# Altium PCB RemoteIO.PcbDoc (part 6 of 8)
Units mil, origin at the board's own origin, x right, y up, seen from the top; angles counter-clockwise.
Board outline 7874.02 x 2362.2 mil, 6 copper layers (Top Layer, GND1, Layer 2, PWR, GND2, Bottom Layer), stack 60.956 mil thick; 655 components, 447 nets, 2607 pads, 1444 vias.
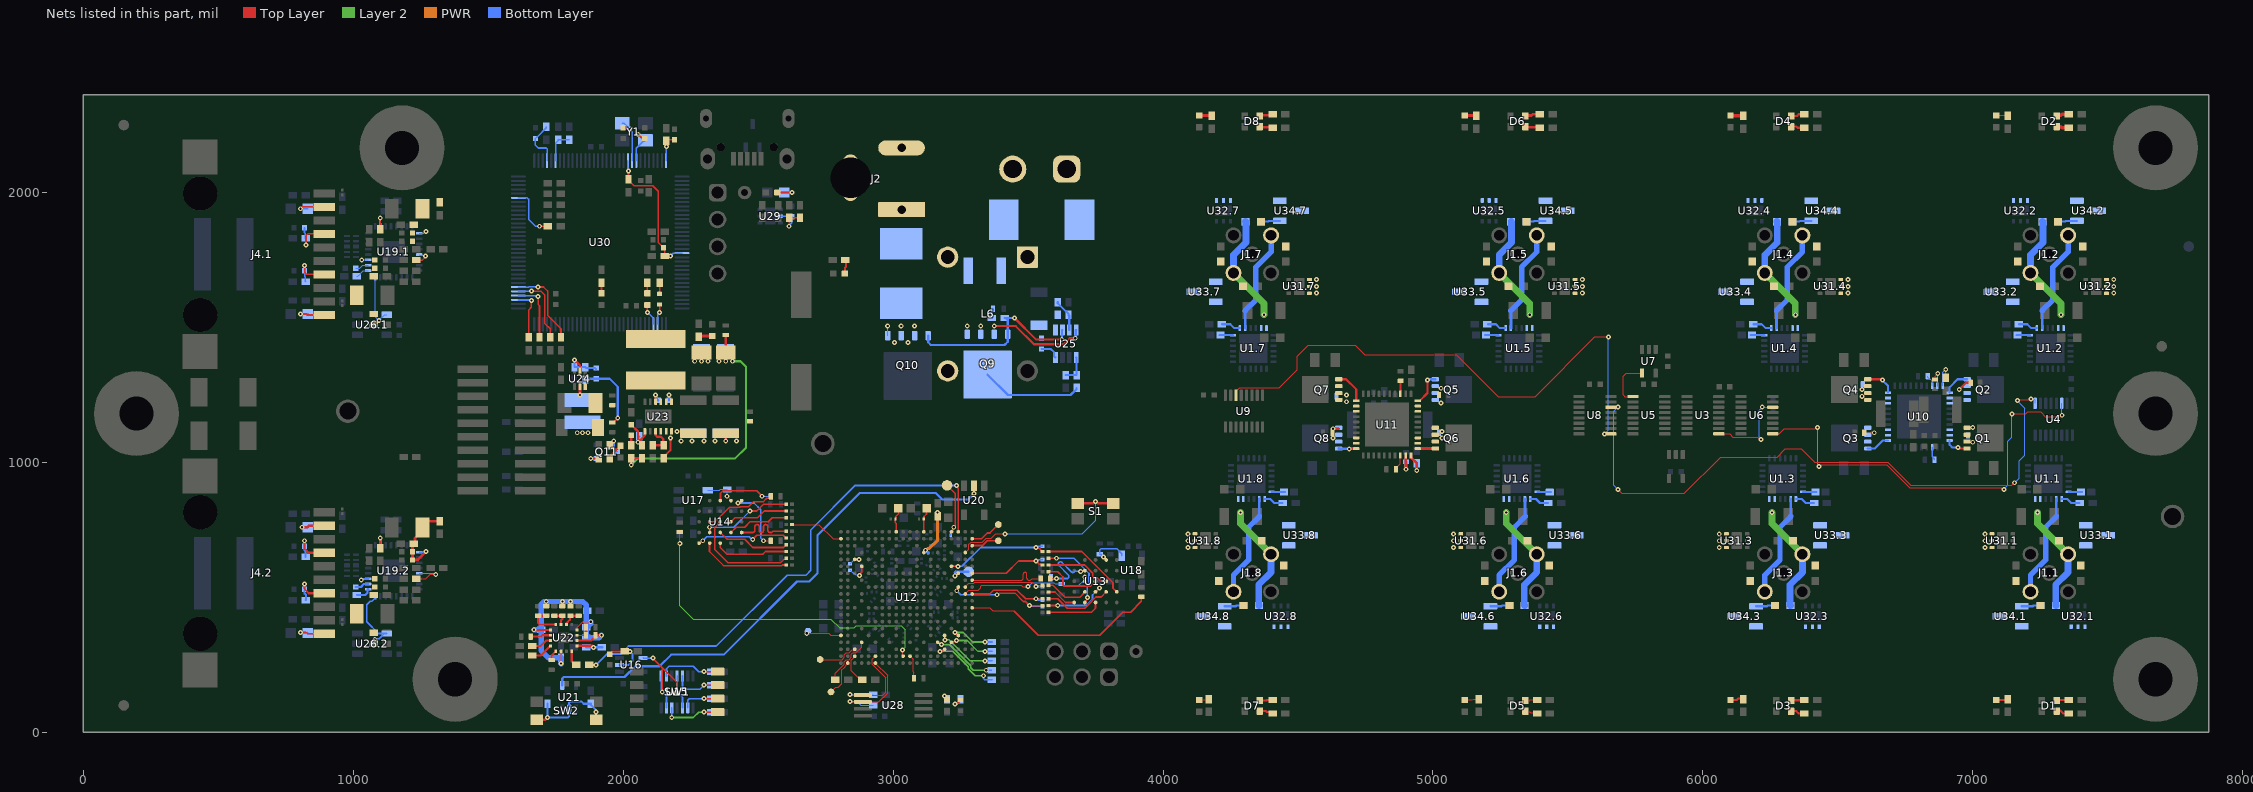
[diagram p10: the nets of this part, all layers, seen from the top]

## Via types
v1: diameter 18, hole 8, Top Layer to Bottom Layer, tented both sides, 1277 vias
v2: diameter 19.68, hole 7.87, Top Layer to Bottom Layer, tented both sides, 133 vias
v3: diameter 19.68, hole 7.87, Top Layer to Bottom Layer, 34 vias

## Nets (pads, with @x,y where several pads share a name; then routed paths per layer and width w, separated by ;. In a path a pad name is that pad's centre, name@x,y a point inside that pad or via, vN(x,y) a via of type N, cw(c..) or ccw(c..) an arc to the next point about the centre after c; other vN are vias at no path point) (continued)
NetC31_2: C31.2 R93.2 U16.2 | length 173.7
  Top Layer w6.45: C31.2@1950,289.69 1960.31,300 R93.2@2006.38,300 v1(2024.87,300)
  Bottom Layer w6.45: U16.2@1985.71,250 2020,250 2034.87,264.87 2034.87,290 v1(2024.87,300)
NetC35_1: C35.1 R100.1 SW2.2 SW2.4 U21.2 | length 381.1
  Top Layer w8: SW2.4@1679.76,46.54 1711.54,46.54 v1(1720,55) ; v1(1900,75) 1900,46.77 SW2.2@1900.24,46.54
  Bottom Layer w8: C35.1@1720,106.38 v1(1720,55) 1795,55 1800,60 U21.2@1800,85.71 1800,110 1805,115 1845,115 1853.62,106.38 R100.1@1880,106.38 1880,102.44 1900,82.44 v1(1900,75)
NetC39_1: C39.1 C41.1 C42.1 C43.1 L1.1 R101.2 R102.2 R103.2 R104.2 U22.5 U22.10 U22.14 U22.16 | length 1028.6
  Top Layer w4: v1(1770,255) 1770.16,255.16 U22.10@1770.16,300.79 ; U22.16@1829.21,379.53 1829.21,389.21 1850,410 v1(1880,410)
  Top Layer w8: v1(1670,380) 1670.47,379.53 U22.5@1730.79,379.53 ; R103.2@1715,467.72 v1(1715,485) ; R104.2@1775,467.72 v1(1775,485) ; R102.2@1805,467.72 v1(1805,485) ; U22.14@1829.21,340.16 1881.81,340.16 1897.72,356.06 R101.2@1897.72,360 v1(1920,360)
  Bottom Layer w4: 1863.62,430 1867.56,430 ; v1@1877.37,412.63 v1(1880,410)
  Bottom Layer w20: v1(1670,380) C39.1@1696.38,380 ; v1(1770,255) C41.1@1770,276.38 1723.62,276.38 1696.38,303.62 C39.1@1696.38,380 ; v1(1880,410) 1880,402.44 1867.56,390 C43.1@1863.62,390 ; v1(1920,360) 1910,350 C42.1@1863.62,350 C43.1@1863.62,390 ; C39.1@1696.38,380 1696.38,474.66 1706.72,485 v1(1715,485) v1(1775,485) v1(1805,485) 1850,485 1863.62,471.38 1863.62,430 C43.1@1863.62,390
NetC79_2: C79.2 L2.1 U12.U8 | length 188.7
  Top Layer w10: U12.U8@3113.98,666.34 3113.98,667.36 3120,673.39 v1(3120,675)
  PWR w10: v1(3120,675) 3122.16,675 3128.17,681.01 3134.2,681.01 3136.59,683.41
  PWR w12: 3136.59,683.41 3165,711.81 v1(3165,815)
  Bottom Layer w10: v1(3120,675) C79.2@3130,665
NetC81_2: C81.2 TP1.1 U12.Y4 | length 224.7
  Top Layer w6: TP1.1@3200,915 3230,885 v1@3230,760 ; U12.Y4@3216.34,743.11 3216.34,745.22 3222.7,751.58 3222.7,757.7 v1(3225,760)
  Bottom Layer w6: C81.2@3213.66,730 3213.66,743.66 v1@3230,760
NetC82_2: C82.2 TP2.1 U12.P3 | length 79.8
  Top Layer w8: v1(3230,580) 3231.18,580 3240.75,589.57 U12.P3@3241.93,589.57
  Bottom Layer w8: v1(3230,580) 3229.87,580.13 3229.87,592.62 C82.2@3231.12,593.88 3232.38,595.13 3279.87,595.13 TP2.1@3280,595
NetC103_1: C103.1 L4.1 U23.1 U23.2 U23.3 | length 67.3
  Top Layer w8: L4.1@2120,1303.23 2125.54,1303.23 L4.1@2155,1273.76
  Bottom Layer w8: C103.1@2169.68,1230 2169.68,1249.68 v1(2170,1250)
NetC103_2: C103.2 U23.4 | length 49.6
  Top Layer w8: v1(2120,1250) 2120.08,1249.92 2120.08,1224.8 U23.4@2120.16,1224.72
  Bottom Layer w8: v1(2120,1250) 2120,1247.29 2124.47,1242.82 2124.47,1235.85 C103.2@2130.31,1230
NetC104_2: C104.2 C105.2 C106.2 C107.2 R134.2 R137.1 U23.10 U23.11 U23.12 | length 113
  Top Layer w8: R134.2@2150,1016.38 2150,1020.32 2175,1045.32 v1(2175,1090) ; v1(2380,1080) C106.2@2380,1108.98
  other v1: 2215,1080 2255,1080 2300,1080 2340,1080 2420,1080 2200,1115
NetC108_1: C108.1 C109.1 C110.1 C111.1 L4.2 R117.1 R122.2 R123.2 | length 983.7
  Top Layer w8: v1(2030,990) R123.2@2030,1016.38 R122.2@2070,1016.38 ; C110.1@2380,1407.09 R117.1@2380,1472.28
  Layer 2 w8: v1(2030,990) 2055,1015 2415,1015 2455,1055 2455,1355 2435,1375 v1(2405,1375)
  Bottom Layer w8: v1(2290,1375) C109.1@2290,1416.93
  other v1: 2265,1375 2315,1375 2355,1375 2380,1375
NetC112_1: C112.1 R122.1 R124.2 U23.7 | length 144.8
  Top Layer w8: C112.1@2030,1139.68 2055,1114.68 2055,1084.12 ; 2056.91,1084.12 2056.91,1076.91 2079.87,1099.87 2079.87,1114.35 U23.7@2080.79,1115.28
  Bottom Layer w8: v1(2055,1075) 2056.91,1076.91 2056.91,1093.29 R124.2@2060,1096.38
NetC112_2: C112.2 R123.1 | length 36.7
  Top Layer w8: R123.1@2030,1063.62 C112.2@2030,1100.32
NetC113_1: C113.1 R139.1 U24.3
NetC114_1: C114.1 R126.1 R128.2 U24.5 | length 159.1
  Top Layer w8: v1(1820,1380) 1840,1360 U24.5@1840,1339.13
  Bottom Layer w8: v1(1820,1380) R128.2@1820,1353.62 R126.1@1860,1353.62 1863.94,1349.68 1895.32,1349.68 C114.1@1900,1345
NetC114_2: C114.2 C115.1 L5.2 R125.1 R126.2 | length 277.1
  Top Layer w8: R125.1@1960,1147.72 1963.94,1147.72 1980,1163.78 v1(1980,1165)
  Bottom Layer w8: R126.2@1860,1306.38 1863.94,1310.32 1899.68,1310.32 1900,1310 1950,1310 1980,1280 v1(1980,1165)
  other v1: 1830,1110 1850,1110 1870,1110
NetC117_1: C117.1 U25.4 | length 73.2
  Bottom Layer w8: C117.1@3550,1420.32 3584.68,1420.32 3596.76,1408.24 3596.76,1393.68 U25.4@3601.61,1388.82
NetC117_2: C117.2 C118.2 L6.3 Q9.5 Q9.6 Q9.7 Q9.8 Q9.9@3350,1325.47 R129.2 R130.2 U25.5 | length 374.5
  Bottom Layer w8: Q9.9@3350,1325.47 3425.47,1250 3657.56,1250 3680,1272.44 R130.2@3680,1276.38
NetC119_2: C119.2 R131.1 | length 36.5
  Bottom Layer w8: R131.1@3366.38,1535 3366.38,1561.88 3370,1565.5 C119.2@3370,1570
NetC120_1: C120.1 D25.1 J2.2 J2.3 J5.1 L6.1
NetC120_2: C120.2 F1.1 L6.2
NetC123_2: C123.2 C124.2 U12.Y8 | length 91.3
  Top Layer w6: C124.2@3113.66,790 3114.71,791.05 3114.71,799.71 3123.77,808.77 3123.77,828.77 C123.2@3125,830 ; U12.Y8@3113.98,743.11 C124.2@3113.98,789.68
NetC125_2: C125.2 C126.2 U12.Y12 | length 93.9
  Top Layer w6: U12.Y12@3011.61,743.11 3011.61,773.39 3008.66,776.34 C126.2@3008.66,790 3009.71,791.05 3009.71,799.71 3021.13,811.13 3021.13,828.4 C125.2@3019.53,830
NetC128.1_2: C128.1.2 U19.1.2 | length 50.3
  Bottom Layer w4: C128.1.2@1009.69,1720 1025,1720 1035.79,1730.79 U19.1.2@1055.51,1730.79
NetC128.2_2: C128.2.2 U19.2.2 | length 50.3
  Bottom Layer w8: C128.2.2@1009.69,538.89 1028.71,538.89 1039.23,549.42 1055.24,549.42 U19.2.2@1055.51,549.68
NetC129.1_1: C129.1.1 C130.1.1 C131.1.2 C135.1.2 L7.1.1 U19.1.3 | length 23.8
  Bottom Layer w4: v1(1031.8,1750.66) 1031.89,1750.56 1055.42,1750.56 U19.1.3@1055.51,1750.47
NetC129.2_1: C129.2.1 C130.2.1 C131.2.2 C135.2.2 L7.2.1 U19.2.3 | length 27.3
  Bottom Layer w8: v1(1030,565) 1032.71,565 1036.35,568.65 1054.79,568.65 U19.2.3@1055.51,569.37
NetC132.1_1: C132.1.1 C133.1.1 C134.1.2 C137.1.2 L8.1.1 U19.1.17 | length 28
  Bottom Layer w4: U19.1.17@1244.49,1848.9 1261.19,1848.9 1267.29,1855 v1(1270,1855)
NetC132.2_1: C132.2.1 C133.2.1 C134.2.2 C137.2.2 L8.2.1 U19.2.17 | length 299.6
  Top Layer w10: v1(1270,670) 1238.9,638.9 C137.2.2@1219.69,638.9 C134.2.2@1219.69,668.9 1219.69,694.96 C133.2.1@1223.62,698.9 1228.87,704.14 1228.87,719.85 1257.09,748.07 C132.2.1@1257.09,758.9 1257.09,761.93 1277.68,782.52 L8.2.1@1320,782.52
  Bottom Layer w5: U19.2.17@1244.49,667.8 1267.8,667.8 v1(1270,670)
NetC136.1_1: C136.1.1 C139.1.2 J4.1.4 | length 172.9
  Top Layer w6: v1(825,1805) 825,1840 831.65,1846.65 J4.1.4@892.91,1846.65
  Bottom Layer w6: C139.1.2@819.69,1870 819.69,1850.31 822.7,1847.3 822.7,1830.92 C136.1.1@823.62,1830 825,1828.62 v1(825,1805)
NetC136.2_1: C136.2.1 C139.2.2 J4.2.4 | length 170.7
  Top Layer w8: v1(820,710) 820,680 834.45,665.55 J4.2.4@892.91,665.55
  Bottom Layer w8: v1(820,710) 819.84,709.84 819.84,690.15 C139.2.2@819.69,690 820,689.68 820,675 823.62,671.38 C136.2.1@823.62,650
NetC138.1_1: C138.1.1 C141.1.2 J4.1.7 | length 163.1
  Top Layer w6: v1(820,1730) 820,1705 828.35,1696.65 J4.1.7@892.91,1696.65
  Bottom Layer w6: v1(820,1730) 820,1710.31 C141.1.2@819.69,1710 820,1709.68 820,1690 822.7,1687.3 822.7,1670.92 C138.1.1@823.62,1670
NetC138.2_1: C138.2.1 C141.2.2 J4.2.7 | length 161.4
  Top Layer w8: v1(820,550) 820,530.72 835.17,515.55 J4.2.7@892.91,515.55
  Bottom Layer w8: v1(820,550) 819.84,549.84 819.84,530.15 C141.2.2@819.69,530 819.69,514.69 825,509.37 825,491.38 C138.2.1@823.62,490
NetC145_1: C145.1 R194.1 R196.2 U29.2 | length 153.3
  Top Layer w6: v1(2615,1875) R194.1@2615,1906.38 R196.2@2655,1906.38
  Bottom Layer w6: U29.2@2583.39,1912.28 2623.04,1912.28 C145.1@2625,1910.32 2625,1888.25 2615,1878.25 v1(2615,1875)
NetC147_2: C147.2 R201.2 U30.96 | length 105.2
  Top Layer w6: v1(2160,2170) R201.2@2160,2191.38 2163.94,2195.31 C147.2@2190,2195.31
  Bottom Layer w6: U30.96@2159.09,2118.15 2159.45,2118.51 2159.45,2169.45 v1(2160,2170)
NetC157_2: C157.2 C158.1 C159.1 U30.87 U30.115 | length 511
  Top Layer w6: C158.1@2020,2045 2020,2044.68 2028.81,2035.87 2029.13,2035.87 2040,2025 2110,2025 2130,2005 2130,1814.69 C157.2@2149.69,1795 ; C158.1@2020,2048.62 v1@2020,2075 ; C157.2@2150,1795 2153.62,1791.38 C159.1@2153.62,1765 v1(2175,1765)
  Bottom Layer w6: U30.87@2017.36,2118.15 2017.36,2082.64 v1(2020,2080) ; v1(2175,1765) 2185.27,1775.27 2217.79,1775.27 U30.115@2218.15,1775.63
NetC160_2: C160.2 U30.88 Y1.3 | length 183.8
  Top Layer w6: C160.2@2000,2239.68 2017.07,2239.68 2021.75,2235 v1(2025,2235)
  Bottom Layer w6: Y1.3@1996.69,2256.5 2003.5,2256.5 v1(2025,2235) ; v1@2024.06,2234.06 2033.11,2225 U30.88@2033.11,2118.15
NetC161_2: C161.2 U30.89 Y1.1 | length 156
  Top Layer w6: v1(2055,2215) 2065.51,2204.49 2075.83,2204.49 C161.2@2080,2200.32
  Bottom Layer w6: U30.89@2048.86,2118.15 2048.86,2163.98 2074.88,2190 Y1.1@2080,2190 ; v1(2055,2215) 2076.5,2193.5 Y1.1@2083.31,2193.5
NetC162_2: C162.2 R211.1 U30.68 | length 177.3
  Bottom Layer w6: C162.2@1675,2200 1675,2175 1685,2165 1714.63,2165 1718.15,2161.49 U30.68@1718.15,2118.15 ; C162.2@1675,2200.31 1681.84,2207.16 1682.47,2207.16 1715,2239.68 R211.1@1715,2243.62
NetC164_1: C164.1 L9.1 U22.13 | length 120.8
  Top Layer w10: U22.13@1829.21,320.47 1884.53,320.47 v1(1890,315)
  Bottom Layer w10: C164.1@1863.62,315 v1(1890,315) L9.1@1921.38,315
NetD1_3: D1.3 R3.1 | length 48.6
  Top Layer w8: D1.3@7311.02,78.74 7312.28,80 7325,80 7335,70 R3.1@7355,70
NetD1_4: D1.4 R4.1 | length 44.1
  Top Layer w8: D1.4@7315,115 7315,116.17 7318.83,120 R4.1@7356.38,120
NetD2_3: D2.3 R5.1 | length 47.8
  Top Layer w12: D2.3@7311.02,2244.09 7311.93,2245 7325,2245 7330,2240 R5.1@7356.38,2240
NetD2_4: D2.4 R6.1 | length 48.1
  Top Layer w12: D2.4@7311.02,2283.46 7312.56,2285 7325,2285 7330,2290 R6.1@7356.38,2290
NetD3_3: D3.3 R7.1 | length 53.2
  Top Layer w8: D3.3@6326.77,78.74 6346.26,78.74 6355,70 R7.1@6376.38,70
NetD3_4: D3.4 R8.1 | length 50.4
  Top Layer w8: D3.4@6326.77,118.11 6327.72,119.06 6375.43,119.06 R8.1@6376.38,120
NetD4_3: D4.3 R9.1 | length 51.3
  Top Layer w8: D4.3@6326.77,2244.09 6345.91,2244.09 6350,2240 R9.1@6376.38,2240
NetD4_4: D4.4 R10.1 | length 52.3
  Top Layer w8: D4.4@6326.77,2283.46 6348.46,2283.46 6355,2290 R10.1@6376.38,2290
NetD5_3: D5.3 R11.1 | length 47.5
  Top Layer w4: D5.3@5342.52,78.74 5344.25,77.01 5357.99,77.01 5362.66,72.34 5384.03,72.34 R11.1@5386.38,70
NetD5_4: D5.4 R12.1 | length 44.6
  Top Layer w4: D5.4@5342.52,118.11 5358.11,118.11 5360,120 R12.1@5386.38,120
NetD6_3: D6.3 R13.1 | length 56.2
  Top Layer w10: D6.3@5342.52,2244.09 5344.57,2242.05 5387.95,2242.05 R13.1@5395,2235
NetD6_4: D6.4 R14.1 | length 55.2
  Top Layer w10: D6.4@5342.52,2283.46 5344.06,2285 5365,2285 5370,2290 R14.1@5395,2290
NetD7_3: D7.3 R15.1 | length 51.7
  Top Layer w8: D7.3@4358.27,78.74 4381.26,78.74 4383.92,76.08 4400.3,76.08 R15.1@4406.38,70
NetD7_4: D7.4 R16.1 | length 48.9
  Top Layer w8: D7.4@4358.27,118.11 4383.11,118.11 4385,120 R16.1@4406.38,120
NetD8_3: D8.3 R17.1 | length 55.5
  Top Layer w10: D8.3@4358.27,2244.09 4360.32,2242.05 4402.95,2242.05 R17.1@4410,2235
NetD8_4: D8.4 R18.1 | length 49.4
  Top Layer w10: D8.4@4358.27,2283.46 4361.54,2286.73 4401.73,2286.73 R18.1@4405,2290
NetD9_2: D9.2 R19.1 | length 43.4
  Top Layer w8: D9.2@7086.61,120.08 7129.92,120.08 R19.1@7130,120
NetD10_2: D10.2 R20.1 | length 44.1
  Top Layer w4: D10.2@7086.61,2285.43 7128.19,2285.43 R20.1@7130,2283.62
NetD11_2: D11.2 R21.1 | length 50.2
  Top Layer w8: D11.2@6102.36,120.08 6125.08,120.08 6130,125 6148.62,125 R21.1@6150,123.62
NetD12_2: D12.2 R22.1 | length 48.4
  Top Layer w12: D12.2@6102.36,2285.43 6103.27,2284.53 6149.09,2284.53 R22.1@6150,2283.62
NetD13_2: D13.2 R23.1 | length 53.4
  Top Layer w4: D13.2@5118.11,120.08 5118.19,120 5145,120 5148.62,123.62 R23.1@5170,123.62
NetD14_2: D14.2 R24.1 | length 45.9
  Top Layer w10: D14.2@5115,2285 5115.43,2285.43 D14.2@5118.11,2285.43 5158.19,2285.43 R24.1@5160,2283.62
NetD15_2: D15.2 R25.1 | length 37.6
  Top Layer w4: D15.2@4133.86,120.08 4166.46,120.08 R25.1@4170,123.62
NetD16_2: D16.2 R26.1 | length 45.9
  Top Layer w10: D16.2@4135,2285 4135.43,2285.43 4178.19,2285.43 R26.1@4180,2283.62
NetD20_1: D20.1 R136.2 | length 52
  Top Layer w8: D20.1@2821.65,1700 2821.65,1721.65 2825,1725 2825,1748.62 R136.2@2823.62,1750
NetD21_1: D21.1 R138.2 | length 50.8
  Top Layer w10: R138.2@2280,1466.38 2281.97,1468.35 D21.1@2330,1468.35
NetD22_1: D22.1 R140.2 | length 61.8
  Top Layer w8: R140.2@1950,1016.38 1957.81,1024.19 1957.81,1029.46 D22.1@1990,1061.65
NetD23_1: D23.1 R143.2 | length 49.3
  Top Layer w8: v1@3236.05,106.91 3248.82,119.68 D23.1@3250,119.68
  Bottom Layer w8: v1(3230,105) 3231.91,106.91 3237.23,106.91 3250,119.68 R143.2@3250,123.62
NetD24_1: D24.1 R142.2 | length 17.5
  Top Layer w8: v1(3190,135) 3190,132.29 3192.19,130.11 3192.19,129.46 D24.1@3200,121.65
NetD25_2: D25.2 F1.2 J2.1 J5.2
NetD28_1: D28.1 R206.2 | length 42.4
  Top Layer w6: D28.1@2135,1624.68 2135,1660 R206.2@2140,1665
NetD28_2: D28.2 U30.3 | length 76.5
  Top Layer w6: v1(2135,1555) D28.2@2135,1585.32
  Bottom Layer w6: U30.3@2127.6,1511.85 2127.6,1547.6 v1(2135,1555)
NetD29_1: D29.1 R207.2 | length 43.3
  Top Layer w6: D29.1@2090,1626.65 R207.2@2090,1666.38 R207.2@2090,1670
NetD29_2: D29.2 U30.4 | length 81.9
  Top Layer w6: v1(2090,1555) D29.2@2090,1583.35
  Bottom Layer w6: v1(2090,1555) 2092.32,1555 2111.85,1535.47 U30.4@2111.85,1511.85
NetD30_1: D30.1 R195.2 | length 43.3
  Top Layer w6: D30.1@1920,1626.65 R195.2@1920,1666.38 R195.2@1920,1670
NetD31_1: D31.1 R213.2 | length 81.9
  Top Layer w6: D31.1@2571.61,2000 v1(2625,2000)
  Bottom Layer w6: R213.2@2596.5,2000 v1(2625,2000)
NetJ1.1_2: J1.1.2 RV1.1.1 RV4.1.2 RV5.1.2 U1.1.11 U1.1.12 U33.1.1 U33.1.2 | length 411.7
  Layer 2 w25: v1(7240,815) 7240,773.21 J1.1.2@7353.06,660.15
  Bottom Layer w25: RV5.1.2@7308.54,470 7308.31,470 7307.03,471.28 7307.03,547.03 7353.06,593.06 J1.1.2@7353.06,660.15
NetJ1.1_4: J1.1.4 RV2.1.1 RV5.1.1 RV6.1.1 U1.1.8 U34.1.1 U34.1.2 | length 454.9
  Bottom Layer w8: U34.1.1@7181.34,467.4 7222.4,467.4 7225,470 RV5.1.1@7250,470 ; J1.1.4@7212.91,520 J1.1.4@7213.87,520.95
  Bottom Layer w10: U1.1.8@7309.53,864.7 7309.53,800.47 7310,800
  Bottom Layer w20: J1.1.4@7213.87,520.95 7213.87,582.51 7270,638.64 7270,760 7310,800
NetJ1.2_2: J1.2.2 RV1.2.1 RV4.2.2 RV5.2.2 U1.2.11 U1.2.12 U33.2.1 U33.2.2 | length 411.7
  Layer 2 w25: J1.2.2@7213.87,1702.06 7326.93,1588.99 v1(7326.93,1547.2)
  Bottom Layer w25: J1.2.2@7213.87,1702.06 7213.87,1769.14 7259.9,1815.17 7259.9,1890.93 7258.62,1892.2 RV5.2.2@7258.39,1892.2
NetJ1.2_4: J1.2.4 RV2.2.1 RV5.2.1 RV6.2.1 U1.2.8 U34.2.1 U34.2.2 | length 454.9
  Bottom Layer w8: RV5.2.1@7316.93,1892.2 7341.93,1892.2 7344.53,1894.8 U34.2.1@7385.59,1894.8 ; J1.2.4@7353.06,1841.25 J1.2.4@7354.02,1842.2
  Bottom Layer w10: 7256.93,1562.2 7257.4,1561.73 U1.2.8@7257.4,1497.5
  Bottom Layer w20: 7256.93,1562.2 7296.93,1602.2 7296.93,1723.56 7353.06,1779.69 J1.2.4@7353.06,1841.25
NetJ1.3_2: J1.3.2 RV1.3.1 RV4.3.2 RV5.3.2 U1.3.11 U1.3.12 U33.3.1 U33.3.2 | length 411.7
  Layer 2 w25: v1(6255.75,815) 6255.75,773.21 J1.3.2@6368.81,660.15
  Bottom Layer w25: RV5.3.2@6324.29,470 6324.06,470 6322.78,471.28 6322.78,547.03 6368.81,593.06 J1.3.2@6368.81,660.15
NetJ1.3_4: J1.3.4 RV2.3.1 RV5.3.1 RV6.3.1 U1.3.8 U34.3.1 U34.3.2 | length 454.9
  Bottom Layer w8: U34.3.1@6197.09,467.4 6238.15,467.4 6240.75,470 RV5.3.1@6265.75,470 ; J1.3.4@6228.66,520 J1.3.4@6229.62,520.95
  Bottom Layer w10: U1.3.8@6325.28,864.7 6325.28,800.47 6325.75,800
  Bottom Layer w20: J1.3.4@6229.62,520.95 6229.62,582.51 6285.75,638.64 6285.75,760 6325.75,800
NetJ1.4_2: J1.4.2 RV1.4.1 RV4.4.2 RV5.4.2 U1.4.11 U1.4.12 U33.4.1 U33.4.2 | length 411.7
  Layer 2 w25: J1.4.2@6229.62,1702.06 6342.68,1588.99 v1(6342.68,1547.2)
  Bottom Layer w25: J1.4.2@6229.62,1702.06 6229.62,1769.14 6275.64,1815.17 6275.64,1890.93 6274.36,1892.2 RV5.4.2@6274.13,1892.2
NetJ1.4_4: J1.4.4 RV2.4.1 RV5.4.1 RV6.4.1 U1.4.8 U34.4.1 U34.4.2 | length 454.9
  Bottom Layer w8: RV5.4.1@6332.68,1892.2 6357.68,1892.2 6360.28,1894.8 U34.4.1@6401.34,1894.8 ; J1.4.4@6368.81,1841.25 J1.4.4@6369.76,1842.2
  Bottom Layer w10: 6272.68,1562.2 6273.15,1561.73 U1.4.8@6273.15,1497.5
  Bottom Layer w20: 6272.68,1562.2 6312.68,1602.2 6312.68,1723.56 6368.81,1779.69 J1.4.4@6368.81,1841.25
NetJ1.5_2: J1.5.2 RV1.5.1 RV4.5.2 RV5.5.2 U1.5.11 U1.5.12 U33.5.1 U33.5.2 | length 411.7
  Layer 2 w25: J1.5.2@5245.36,1702.06 5358.43,1588.99 v1(5358.43,1547.2)
  Bottom Layer w25: J1.5.2@5245.36,1702.06 5245.36,1769.14 5291.39,1815.17 5291.39,1890.93 5290.11,1892.2 RV5.5.2@5289.88,1892.2
NetJ1.5_4: J1.5.4 RV2.5.1 RV5.5.1 RV6.5.1 U1.5.8 U34.5.1 U34.5.2 | length 454.9
  Bottom Layer w8: RV5.5.1@5348.43,1892.2 5373.43,1892.2 5376.02,1894.8 U34.5.1@5417.09,1894.8 ; J1.5.4@5384.56,1841.25 J1.5.4@5385.51,1842.2
  Bottom Layer w10: 5288.43,1562.2 5288.9,1561.73 U1.5.8@5288.9,1497.5
  Bottom Layer w20: 5288.43,1562.2 5328.43,1602.2 5328.43,1723.56 5384.56,1779.69 J1.5.4@5384.56,1841.25
NetJ1.6_2: J1.6.2 RV1.6.1 RV4.6.2 RV5.6.2 U1.6.11 U1.6.12 U33.6.1 U33.6.2 | length 411.7
  Layer 2 w25: v1(5271.5,815) 5271.5,773.21 J1.6.2@5384.56,660.15
  Bottom Layer w25: RV5.6.2@5340.04,470 5339.81,470 5338.53,471.28 5338.53,547.03 5384.56,593.06 J1.6.2@5384.56,660.15
NetJ1.6_4: J1.6.4 RV2.6.1 RV5.6.1 RV6.6.1 U1.6.8 U34.6.1 U34.6.2 | length 454.9
  Bottom Layer w8: U34.6.1@5212.83,467.4 5253.9,467.4 5256.5,470 RV5.6.1@5281.5,470 ; J1.6.4@5244.41,520 J1.6.4@5245.36,520.95
  Bottom Layer w10: U1.6.8@5341.02,864.7 5341.02,800.47 5341.5,800
  Bottom Layer w20: J1.6.4@5245.36,520.95 5245.36,582.51 5301.5,638.64 5301.5,760 5341.5,800
NetJ1.7_2: J1.7.2 RV1.7.1 RV4.7.2 RV5.7.2 U1.7.11 U1.7.12 U33.7.1 U33.7.2 | length 411.7
  Layer 2 w25: J1.7.2@4261.11,1702.06 4374.17,1588.99 v1(4374.17,1547.2)
  Bottom Layer w25: J1.7.2@4261.11,1702.06 4261.11,1769.14 4307.14,1815.17 4307.14,1890.93 4305.86,1892.2 RV5.7.2@4305.63,1892.2
NetJ1.7_4: J1.7.4 RV2.7.1 RV5.7.1 RV6.7.1 U1.7.8 U34.7.1 U34.7.2 | length 454.9
  Bottom Layer w8: RV5.7.1@4364.17,1892.2 4389.17,1892.2 4391.77,1894.8 U34.7.1@4432.83,1894.8 ; J1.7.4@4400.31,1841.25 J1.7.4@4401.26,1842.2
  Bottom Layer w10: 4304.17,1562.2 4304.65,1561.73 U1.7.8@4304.65,1497.5
  Bottom Layer w20: 4304.17,1562.2 4344.17,1602.2 4344.17,1723.56 4400.31,1779.69 J1.7.4@4400.31,1841.25
NetJ1.8_2: J1.8.2 RV1.8.1 RV4.8.2 RV5.8.2 U1.8.11 U1.8.12 U33.8.1 U33.8.2 | length 411.7
  Layer 2 w25: v1(4287.24,815) 4287.24,773.21 J1.8.2@4400.31,660.15
  Bottom Layer w25: RV5.8.2@4355.79,470 4355.56,470 4354.28,471.28 4354.28,547.03 4400.31,593.06 J1.8.2@4400.31,660.15
NetJ1.8_4: J1.8.4 RV2.8.1 RV5.8.1 RV6.8.1 U1.8.8 U34.8.1 U34.8.2 | length 454.9
  Bottom Layer w8: U34.8.1@4228.58,467.4 4269.65,467.4 4272.24,470 RV5.8.1@4297.24,470 ; J1.8.4@4260.16,520 J1.8.4@4261.11,520.95
  Bottom Layer w10: U1.8.8@4356.77,864.7 4356.77,800.47 4357.24,800
  Bottom Layer w20: J1.8.4@4261.11,520.95 4261.11,582.51 4317.24,638.64 4317.24,760 4357.24,800
NetJ4.1_2: J4.1.2 R192.1.2 | length 117.2
  Top Layer w6: v1(805,1940) 811.65,1946.65 J4.1.2@892.91,1946.65
  Bottom Layer w6: v1(805,1940) R192.1.2@831.5,1940
NetJ4.1_10: J4.1.10 R191.1.2 | length 115.8
  Top Layer w8: v1(805,1550) 825,1550 828.35,1546.65 J4.1.10@892.91,1546.65
  Bottom Layer w8: v1(805,1550) R191.1.2@831.5,1550
NetJ4.2_2: J4.2.2 R192.2.2 | length 106.7
  Top Layer w10: v1(810,760) 830,760 835.55,765.55 J4.2.2@892.91,765.55
  Bottom Layer w10: v1(810,760) R192.2.2@831.5,760
NetJ4.2_10: J4.2.10 R191.2.2 | length 116.7
  Top Layer w6: v1(805,370) 826.1,370 830.55,365.55 J4.2.10@892.91,365.55
  Bottom Layer w6: v1(805,370) 830.39,370 R191.2.2@831.5,368.9
NetL5_1: L5.1 U24.2 | length 30.9
  Top Layer w12: v1(1840,1250) U24.2@1840,1280.87
NetQ1_1: Q1.1 Q1.2 Q1.3 R155.1 U10.38 U10.39 | length 5.9
  Top Layer w8: Q1.2@6973.07,1102.8 Q1.2@6978.58,1102.8 Q1.2@6978.98,1102.8
  other v1: 7000,1075 7000,1130
NetQ1_4: Q1.4 U10.40 | length 81.3
  Top Layer w8: v1(6945,1055) 6948.39,1051.61 Q1.4@6978.58,1051.61 Q1.4@6978.98,1051.61
  Bottom Layer w8: U10.40@6914.17,1081.42 6914.17,1065.83 6925,1055 v1@6940,1055
NetQ2_1: Q2.1 Q2.2 Q2.3 R156.1 U10.32 U10.33 | length 52.6
  Top Layer w8: v1(6950,1270) 6975,1295 R156.1@6992.28,1295
NetQ2_4: Q2.4 U10.31 | length 97.5
  Bottom Layer w8: U10.31@6914.17,1258.58 6914.17,1279.17 6943.39,1308.39 Q2.4@6978.98,1308.39
NetQ3_1: Q3.1 Q3.2 Q3.3 R157.1 U10.12 U10.13 | length 10
  Top Layer w8: 6625,1110 v1(6635,1110)
NetQ3_4: Q3.4 U10.11 | length 87.1
  Bottom Layer w8: Q3.4@6611.02,1051.61 6636.61,1051.61 6666.42,1081.42 U10.11@6685.83,1081.42
NetQ4_1: Q4.1 Q4.2 Q4.3 R158.1 U10.18 U10.19 | length 1.1
  Top Layer w8: Q4.1@6610.22,1230.81 Q4.1@6611.02,1231.61
  other v1: 6590,1245 6590,1270
NetQ4_4: Q4.4 U10.20 | length 115.4
  Top Layer w8: Q4.4@6611.02,1308.39 6666.61,1308.39 v1@6670,1305
  Bottom Layer w8: v1(6665,1305) 6685.83,1284.17 U10.20@6685.83,1258.58
NetQ5_1: Q5.1 Q5.2 Q5.3 R159.1 U11.38 U11.39
  other v1: 5030,1220 5030,1275
NetQ5_4: Q5.4 U11.40 | length 132.7
  Top Layer w8: U11.40@4944.17,1228.58 4951.06,1228.58 4980,1257.52 v1(4980,1305)
  Bottom Layer w8: v1@4975,1300 v1(4980,1305) 4983.39,1308.39 Q5.4@5008.98,1308.39
NetQ6_1: Q6.1 Q6.2 Q6.3 R160.1 U11.32 U11.33
  other v1: 5032.98,1090 5032.98,1115
NetQ6_4: Q6.4 U11.31 | length 66.5
  Top Layer w10: U11.31@4944.17,1051.42 4944.25,1051.5 5008.5,1051.5 Q6.4@5010,1050
NetQ7_1: Q7.1 Q7.2 Q7.3 R161.1 U11.12 U11.13 | length 2.2
  Bottom Layer w10: v1@4678.47,1226.53 v1(4680,1225)
  other v1: 4680,1250
NetQ7_4: Q7.4 U11.11 | length 122.6
  Top Layer w8: Q7.4@4651.02,1308.39 4678.23,1308.39 4715.83,1270.79 U11.11@4715.83,1228.58
NetQ8_1: Q8.1 Q8.2 Q8.3 R162.1 U11.18 U11.19 | length 20
  Top Layer w10: v1(4630,1125) 4650,1125
  other v1: 4630,1090
NetQ8_4: Q8.4 U11.20 | length 66.1
  Top Layer w10: v1(4690,1050) 4691.34,1051.34 4715.75,1051.34 U11.20@4715.83,1051.42
  Bottom Layer w10: Q8.4@4651.02,1051.61 4651.83,1050.81 4689.19,1050.81 v1(4690,1050)
NetQ9_1: Q9.1 Q9.2 Q9.3 Q10.1 Q10.2 Q10.3 U25.8 | length 404.4
  Top Layer w8: v1(3375,1505) 3455,1505 3522,1438 3632.04,1438 3654.04,1460 v1(3675,1460)
  Bottom Layer w4: Q10.1@2980,1470 v1(2980,1505)
  Bottom Layer w8: v1(3675,1460) 3676.69,1461.69 3676.69,1489.49 U25.8@3678.39,1491.18
  other v1: 3005,1445 3055,1445 3030,1505 3080,1505 3275,1505 3325,1505
NetQ9_4: Q9.4 Q10.4 R131.2 U25.6 | length 701.9
  Top Layer w8: v1(3450,1535) 3530,1455 v1(3625,1455)
  Bottom Layer w8: Q10.4@3130,1470 3130.23,1469.77 3130.23,1444.77 3140,1435 3412.98,1435 3425,1447.02 Q9.4@3425,1475.08 3425,1527.19 R131.2@3417.19,1535 ; R131.2@3413.62,1535 R131.2@3417.19,1535 ; v1(3450,1535) R131.2@3417.19,1535 ; v1(3625,1455) 3626.1,1456.1 3626.1,1490.08 U25.6@3627.2,1491.18
NetQ11_1: Q11.1 R141.1 | length 53.4
  Top Layer w8: v1(1880,1015) 1908.62,1015 R141.1@1910,1016.38
  Bottom Layer w8: v1(1880,1015) 1880.59,1014.41 Q11.1@1902.6,1014.41
NetQ11_3: Q11.3 R140.1 | length 70.7
  Top Layer w8: R140.1@1950,1063.62 1950,1067.56 1962.44,1080 v1(1965,1080)
  Bottom Layer w8: v1(1965,1080) 1965,1052.4 1969.59,1047.81 1969.59,1045.25 1974.84,1040 Q11.3@1977.4,1040
NetR1.1_2: R1.1.2 U1.1.6 | length 50
  Bottom Layer w8: U1.1.6@7355.3,890.79 7355.69,890.39 7404.61,890.39 R1.1.2@7405,890
NetR1.2_2: R1.2.2 U1.2.6 | length 50
  Bottom Layer w8: R1.2.2@7161.93,1472.2 7162.32,1471.81 7211.24,1471.81 U1.2.6@7211.63,1471.42
NetR1.3_2: R1.3.2 U1.3.6 | length 50
  Bottom Layer w8: U1.3.6@6371.04,890.79 6371.44,890.39 6420.35,890.39 R1.3.2@6420.75,890
NetR1.4_2: R1.4.2 U1.4.6 | length 50
  Bottom Layer w8: R1.4.2@6177.68,1472.2 6178.07,1471.81 6226.99,1471.81 U1.4.6@6227.38,1471.42
NetR1.5_2: R1.5.2 U1.5.6 | length 50
  Bottom Layer w8: R1.5.2@5193.43,1472.2 5193.82,1471.81 5242.74,1471.81 U1.5.6@5243.13,1471.42
NetR1.6_2: R1.6.2 U1.6.6 | length 50
  Bottom Layer w8: U1.6.6@5386.79,890.79 5387.19,890.39 5436.1,890.39 R1.6.2@5436.5,890
NetR1.7_2: R1.7.2 U1.7.6 | length 50
  Bottom Layer w8: R1.7.2@4209.17,1472.2 4209.57,1471.81 4258.48,1471.81 U1.7.6@4258.88,1471.42
NetR1.8_2: R1.8.2 U1.8.6 | length 50
  Bottom Layer w8: U1.8.6@4402.54,890.79 4402.93,890.39 4451.85,890.39 R1.8.2@4452.24,890
NetR2.1_2: R2.1.2 U1.1.7 | length 71.9
  Bottom Layer w8: U1.1.7@7329.21,864.7 7350.3,864.7 7365,850 R2.1.2@7395,850
NetR2.2_2: R2.2.2 U1.2.7 | length 71.9
  Bottom Layer w8: R2.2.2@7171.93,1512.2 7201.93,1512.2 7216.63,1497.5 U1.2.7@7237.72,1497.5
NetR2.3_2: R2.3.2 U1.3.7 | length 71.9
  Bottom Layer w8: U1.3.7@6344.96,864.7 6366.04,864.7 6380.75,850 R2.3.2@6410.75,850
NetR2.4_2: R2.4.2 U1.4.7 | length 71.9
  Bottom Layer w8: R2.4.2@6187.68,1512.2 6217.68,1512.2 6232.38,1497.5 U1.4.7@6253.46,1497.5
NetR2.5_2: R2.5.2 U1.5.7 | length 71.9
  Bottom Layer w8: R2.5.2@5203.43,1512.2 5233.43,1512.2 5248.13,1497.5 U1.5.7@5269.21,1497.5
NetR2.6_2: R2.6.2 U1.6.7 | length 71.9
  Bottom Layer w8: U1.6.7@5360.71,864.7 5381.79,864.7 5396.5,850 R2.6.2@5426.5,850
NetR2.7_2: R2.7.2 U1.7.7 | length 71.9
  Bottom Layer w8: R2.7.2@4219.17,1512.2 4249.17,1512.2 4263.88,1497.5 U1.7.7@4284.96,1497.5
NetR2.8_2: R2.8.2 U1.8.7 | length 71.9
  Bottom Layer w8: U1.8.7@4376.46,864.7 4397.54,864.7 4412.24,850 R2.8.2@4442.24,850
NetR27_2: R27.2 U10.28 | length 44.1
  Bottom Layer w4: R27.2@6832.72,1320 6832.72,1316.06 6838.59,1310.19 6841.01,1310.19 6849.21,1301.98 U10.28@6849.21,1284.17
NetR28_1: R28.1 U10.3 | length 49.3
  Bottom Layer w6: U10.3@6849.21,1055.83 6849.21,1022.44 6857.72,1013.94 R28.1@6857.72,1010
NetR30_1: R30.1 U10.29 | length 72.7
  Top Layer w4: R30.1@6860,1307.72 6860,1320 v1(6870,1330)
  Bottom Layer w4: U10.29@6868.9,1284.17 6869.45,1284.72 6869.45,1329.45 v1(6870,1330)
NetR31_2: R31.2 U10.30 | length 96.9
  Top Layer w4: R31.2@6900,1313.62 v1(6900,1345)
  Bottom Layer w4: U10.30@6888.58,1284.17 6888.58,1333.58 v1(6900,1345)
NetR33_2: R33.2 U11.28 | length 57.7
  Top Layer w4: R33.2@4862.72,975 4862.72,978.94 4879.21,995.43 U11.28@4879.21,1025.83
NetR34_1: R34.1 U11.3 | length 46.2
  Top Layer w8: U11.3@4879.21,1254.17 4879.61,1254.57 4879.61,1299.61 R34.1@4880,1300
NetR35_2: R35.2 U12.B10 | length 88.6
  Top Layer w4: U12.B10@3062.8,282.48 3075.19,270.09 3075.19,225.19 3075,225 3077.28,222.72 R35.2@3077.28,200
NetR37_1: R37.1 U11.29 | length 78.6
  Top Layer w10: U11.29@4898.9,1025.83 4898.98,1025.75 4898.98,976.02 v1(4900,975)
  Bottom Layer w10: v1(4900,975) R37.1@4900,1002.28
NetR38_2: R38.2 U11.30 | length 86.1
  Top Layer w10: U11.30@4918.58,1025.83 4918.58,1019.09 4940,997.68 v1(4940,970)
  Bottom Layer w10: v1@4940,975 R38.2@4940,996.38
NetR39_1: R39.1 U12.B18 | length 113.9
  Top Layer w4: U12.B18@2858.07,282.48 2858.07,279.94 2845.68,267.55 2845.68,228.11 2868.79,205 2870.29,205 2870.48,204.81 2872.63,204.81 2882.44,195 R39.1@2886.38,195
NetR40_1: R40.1 U12.D17 | length 186.8
  Top Layer w4: R40.1@2786.38,200 2786.38,218.86 2819.28,251.76 2819.28,261.21 2827.35,269.28 2836.8,269.28 2845,277.48 2845,290 2849.87,294.87 2862.39,294.87 2883.66,316.14 U12.D17@2883.66,333.66
NetR52_2: R52.2 U13.C3 | length 220.3
  Top Layer w6: R52.2@3576.02,595 3610,595 3629.37,575.63 3629.37,546 3632.89,542.49 3732.49,542.49 U13.C3@3750,560
NetR53_2: R53.2 U13.D3 | length 245.5
  Top Layer w6: R53.2@3576.02,470 v1(3610,470) ; U13.D3@3750,520.63 3750.31,520.63 3764.69,535 v1(3765,535)
  Bottom Layer w6: v1(3610,470) 3714.84,470 3738.77,493.93 3738.77,508.77 v1(3765,535)
NetR54_2: R54.2 U13.D2 | length 162.8
  Top Layer w5: U13.D2@3710.63,518.95 U13.D2@3710.63,520.63
  Top Layer w6: R54.2@3576.02,545 3592.73,545 3637.73,500 3691.68,500 U13.D2@3710.63,518.95
NetR55_2: R55.2 U13.C4 | length 245.4
  Top Layer w6: R55.2@3576.02,620 3709.64,620 3740,589.64 3740,577.4 3743.51,573.89 3755.75,573.89 3769.64,560 U13.C4@3789.37,560
NetR56_2: R56.2 U13.D4 | length 250.3
  Top Layer w5: 3744.45,494.65 3744.65,494.65
  Top Layer w6: R56.2@3576.02,495 3610,495 3645,460 3710,460 3736.11,486.11 3736.11,487.01 3743.75,494.65 3744.45,494.65 ; 3744.65,494.65 3751.73,501.73 3770.78,501.73 U13.D4@3787.19,518.13
NetR57_2: R57.2 U13.D5 | length 326.1
  Top Layer w6: R57.2@3576.02,670 3699.1,670 3775.48,593.62 3775.48,593.53 3814.85,554.16 3814.85,534.52 U13.D5@3828.74,520.63
NetR58_2: R58.2 U13.E3 | length 194.6
  Top Layer w6: R58.2@3582.88,445 3735,445 3750,460 U13.E3@3750,481.26
NetR59_2: R59.2 U13.E2 | length 287.3
  Top Layer w6: R59.2@3576.02,645 v1(3605,645) ; U13.E2@3710.63,481.26 3710.63,483.37 3717.7,490.44 3717.7,497.7 v1(3720,500)
  Bottom Layer w6: v1(3605,645) 3670,645 3726,589 3726,549.12 3720,543.12 v1(3720,500)
NetR60_2: R60.2 U13.E1 | length 108.7
  Top Layer w6: R60.2@3578.61,520 3600,520 3638.74,481.26 U13.E1@3671.26,481.26
NetR73_2: R73.2 U14.A5 | length 259.8
  Top Layer w4: v1(2425,850) 2425.84,849.16 2429.16,849.16 U14.A5@2438.74,858.74 ; v1(2520,710) R73.2@2547.28,710
  Bottom Layer w6: v1(2425,850) 2485,850 2510,825 2510,720 v1(2520,710)
NetR74_2: R74.2 U14.C3 | length 403
  Top Layer w4: 2595.7,640.7 2599.68,640.7 R74.2@2603.98,645
  Top Layer w6: U14.C3@2360,780 2340,760 2340,676.31 2388.31,628 2583,628 2595.7,640.7
NetR75_2: R75.2 U14.D3 | length 271.6
  Top Layer w4: R75.2@2598.89,689.91 2598.89,690.7 2603.19,695 R75.2@2603.98,695
  Top Layer w6: U14.D3@2360,740.63 2385.63,715 2450,715 2480,685 2593.98,685 R75.2@2598.89,689.91
NetR76_2: R76.2 U14.D2 | length 338.8
  Top Layer w4: v1(2320,760) v1@2320.32,759.68 ; U14.D2@2320.32,740.94 U14.D2@2320.63,740.63
  Top Layer w6: U14.D2@2320.32,740.94 v1@2320.32,759.68 ; v1(2470,820) 2495,820 2520,845 R76.2@2603.98,845
  Bottom Layer w6: v1(2320,760) 2410,760 v1(2470,820)
NetR77_2: R77.2 U14.C4 | length 221.2
  Top Layer w6: U14.C4@2399.37,780 2414.37,795 2497.5,795 2522.5,820 R77.2@2603.98,820
NetR78_2: R78.2 U14.D4 | length 227.1
  Top Layer w6: U14.D4@2399.37,740.63 2418.74,760 2450,760 2470,780 2537.63,780 2552.63,795 R78.2@2603.98,795
NetR79_2: R79.2 U14.D5 | length 258.4
  Top Layer w6: U14.D5@2438.74,740.63 2445,740.63 2480,740.63 ccw(c2480,748.63) 2488,748.63 2488,762 cw(c2496,762) 2504,762 2504,747.96 ccw(c2512,747.96) 2520,747.96 2520,762 cw(c2528,762) 2536,762 2536,748.63 ccw(c2544,748.63) 2544,740.63 2550.63,740.63 2555,745 2565,745 R79.2@2603.98,745
NetR80_2: R80.2 U14.E3 | length 274.7
  Top Layer w6: U14.E3@2360,701.26 2360,685 2385,660 2517.37,660 2527.37,670 R80.2@2603.98,670
NetR81_2: R81.2 U14.E2 | length 337.9
  Top Layer w4: U14.E2@2320,700.63 U14.E2@2320.63,701.26
  Top Layer w6: U14.E2@2320,700.63 2320,670 2372,618 2587.14,618 2589.14,620 R81.2@2603.98,620
NetR82_2: R82.2 U14.E1 | length 347
  Top Layer w4: U14.E1@2281.26,701.26 2281.73,701.26 2290.47,710 v1(2295,710) ; R82.2@2603.19,720 R82.2@2603.98,720
  Top Layer w6: v1(2480,715) 2494.96,729.96 2593.23,729.96 R82.2@2603.19,720
  Bottom Layer w6: v1(2295,710) 2310,725 2466.75,725 2476.75,715 v1(2480,715)
NetR85_2: R85.2 U12.N1 | length 302.3
  Top Layer w4: U12.N1@3293.11,563.98 3445,563.98 3475,563.98 ccw(c3475,570.98) 3482,570.98 3482,585.79 cw(c3489,585.79) 3496,585.79 3496,570.98 ccw(c3503,570.98) 3503,563.98 3508.98,563.98 3515,570 3520,570 R85.2@3547.28,570
NetR86_2: R86.2 U12.W20 | length 202.6
  Top Layer w4: R86.2@2626.02,770 2725,770 2777.48,717.52 U12.W20@2806.89,717.52
NetR87_2: R87.2 U14.C2 | length 267.2
  Top Layer w4: R87.2@2541.41,867.16 2547.28,873.03 R87.2@2547.28,875
  Top Layer w6: U14.C2@2320.63,780 2340,780 2390,830 2390.64,830 2394.64,834 2431.63,834 2433.63,836 2464.79,836 2483.79,855 2520,855 2532.16,867.16 R87.2@2541.41,867.16
NetR88_2: R88.2 U14.A3 | length 226
  Top Layer w4: U14.A3@2360,858.74 U14.A3@2360.61,859.35
  Top Layer w6: U14.A3@2360.61,859.35 2360.61,885.61 2370,895 2495,895 v1(2515,875)
  Bottom Layer w4: v1(2515,875) R88.2@2547.28,875
NetR89_1: R89.1 SW1.5 U15.12 | length 240.7
  Top Layer w6: v1(2300,75) SW1.5@2350,75
  Layer 2 w6: v1(2180,55) 2260,55 2280,75 v1(2300,75)
  Bottom Layer w6: v1(2180,55) 2180.16,55.16 2180.16,90.79 U15.12@2180.32,90.94 ; v1(2300,75) R89.1@2326.38,75
NetR90_1: R90.1 SW1.6 U15.9 | length 167.8
  Top Layer w6: v1(2300,125) SW1.6@2350,125
  Bottom Layer w6: U15.9@2239.37,90.94 2239.37,119.37 2245,125 v1(2300,125) R90.1@2326.38,125
NetR91_1: R91.1 SW1.7 U15.5 | length 205.9
  Top Layer w6: v1(2300,175) SW1.7@2350,175
  Bottom Layer w6: U15.5@2219.68,209.06 2220,208.74 2220,170 2230,160 2285,160 v1(2300,175) R91.1@2326.38,175
NetR92_1: R92.1 SW1.8 U15.2 | length 254.5
  Top Layer w6: v1(2300,225) SW1.8@2350,225
  Bottom Layer w6: U15.2@2160.63,209.06 2160.63,235.63 2170,245 2260,245 2280,225 v1(2300,225) R92.1@2326.38,225
NetR94_1: R94.1 U14.A4 U17.4 | length 121.1
  Top Layer w4: v1(2385,875) 2385,874.06 2399.37,859.68 U14.A4@2399.37,858.74
  Bottom Layer w4: U17.4@2314.13,897.4 2357.4,897.4 2360,900 R94.1@2386.38,900 2385,898.62 v1(2385,875)
NetR96_1: R96.1 U13.A4 U18.4 | length 146.5
  Top Layer w6: v1(3780,650) 3780,649.06 3788.59,640.46 U13.A4@3788.59,636.24
  Bottom Layer w6: R96.1@3765,660 3769.5,660 3779.5,650 v1(3780,650) ; R96.1@3765,665 3765,675 3770,680 3829.61,680 3847.6,662.01 U18.4@3847.6,654.13
NetR98_2: R98.2 U12.J1 | length 735.8
  Top Layer w4: U12.J1@3293.11,461.61 3357.53,461.61 3369.14,450 3448.58,450 3449.29,449.29
  Top Layer w5: 3449.29,449.29 3478.58,420 3538.58,360 3765,360 3850,445 3880,445 3920,485 R98.2@3920,500
NetR99_2: R99.2 U12.B11 | length 1252.9
  Top Layer w4: v1(2210,700) R99.2@2210,742.28 ; v1(3035,305) 3036.1,303.9 3036.1,283.58 U12.B11@3037.2,282.48
  Layer 2 w4: v1(2210,700) 2210,470 2260,420 2770,420 2802.5,387.5 2856.62,387.5 2863.62,394.5 3030.5,394.5 3045,380 3045,316.21 3035,306.21 v1(3035,305)
NetR101_1: R101.1 R105.2 U22.15 | length 63.1
  Top Layer w4: U22.15@1829.21,359.84 R101.1@1862.13,359.84
  Top Layer w6: R101.1@1862.13,359.84 R101.1@1862.28,360 R105.2@1862.28,390
NetR102_1: R102.1 R106.2 U22.2 | length 70.7
  Top Layer w8: U22.2@1789.84,399.21 1791.26,400.63 1791.26,405.28 1802.76,416.79 1802.76,432.28 R102.1@1805,432.28 R106.2@1835,432.28
NetR103_1: R103.1 R107.2 U22.4 | length 141
  Top Layer w8: R107.2@1685,432.28 1685,405 1690.79,399.21 U22.4@1750.47,399.21 1749.68,400 1735,400 ; R107.2@1690,432.28 R103.1@1715,432.28 R103.1@1720,432.28
NetR104_1: R104.1 R108.2 U22.3 | length 65.1
  Top Layer w8: R108.2@1745,432.28 R104.1@1775,432.28 1775,420 1770.16,415.16 U22.3@1770.16,399.21
NetR111_2: R111.2 U22.9 | length 39.5
  Top Layer w8: R111.2@1735,267.72 1735,284.82 1750.47,300.3 U22.9@1750.47,300.79
NetR112_2: R112.2 U22.6 | length 75.1
  Top Layer w8: R112.2@1657.72,355 1695,355 1699.84,359.84 U22.6@1730.79,359.84
NetR114_2: R114.2 U12.T18 | length 54.4
  Top Layer w4: U12.T18@2858.07,640.75 2858.44,640.37 2873.13,640.37 v1(2873.5,640)
  Bottom Layer w4: R114.2@2841.02,625 2841.81,625 2856.81,640 v1(2873.5,640)
NetR115_2: R115.2 U12.R17 | length 80.3
  Top Layer w5: v1(2875.79,581.7) 2875.79,585.22 2883.66,593.08 U12.R17@2883.66,615.16
  Bottom Layer w4: R115.2@2841.02,600 2841.81,600 2852.31,589.5 2856.2,589.5 2861.32,584.38 2874.38,584.38 v1@2875,585
  Bottom Layer w5: v1@2873.74,583.74 v1(2875.79,581.7)
NetR118_1: R118.1 U22.8 | length 82.1
  Top Layer w8: R118.1@1663.62,285 1695.32,285 1728.88,318.57 1728.88,319.06 1730.3,320.47 U22.8@1730.79,320.47
NetR119_1: R119.1 U22.7 | length 75.6
  Top Layer w8: R119.1@1663.62,320 1695,320 1715.16,340.16 U22.7@1730.79,340.16 U22.7@1730.71,340.08
NetR120_1: R120.1 U22.12 | length 60.1
  Top Layer w8: U22.12@1809.53,300.79 1809.53,262.91 1822.44,250 R120.1@1826.38,250
NetR120_2: R120.2 U12.Y3 | length 1893.1
  Top Layer w6.45: R120.2@1880,250 v1(1900,250) ; v1(3235,915) 3235,911.87 3241.93,904.95 U12.Y3@3241.93,743.11
  Bottom Layer w6.45: v1(1900,250) 1940.69,290.69 1990.69,290.69 2020,320 2345,320 2607.5,582.5 2677.5,582.5 2695,600 2695,750 2860,915 v1(3235,915)
NetR129_1: R129.1 R132.2 U25.7 | length 120.5
  Bottom Layer w8: R129.1@3610,1593.62 3610,1589.68 3641.56,1558.13 3642.19,1558.13 3650,1550.32 R132.2@3650,1546.38 3652.8,1543.58 U25.7@3652.8,1491.18
NetR130_1: R130.1 R133.2 U25.1 | length 105.9
  Bottom Layer w8: R133.2@3640,1323.62 R130.1@3680,1323.62 3679.19,1324.43 3679.19,1388.01 U25.1@3678.39,1388.82
NetR134_1: R134.1 R135.2 U23.9 | length 112.6
  Top Layer w8: R135.2@2110,1063.62 R134.1@2150,1063.62 2148.75,1064.87 2148.75,1086.68 2140.43,1095 2125.77,1095 2121.08,1099.69 2121.08,1114.35 U23.9@2120.16,1115.28
NetR144_2: R144.2 U12.E3 | length 167.3
  Top Layer w6: v1(3230,370) 3230.59,370 3241.34,359.25 U12.E3@3241.93,359.25
  Layer 2 w6: v1(3230,370) 3260,370 3295,335 v1(3340,335)
  Bottom Layer w6: v1(3340,335) R144.2@3366.38,335
NetR145_2: R145.2 U12.B15 U28.5 | length 383
  Top Layer w4: v1(2840,140) 2841.61,138.39 U28.5@2887.8,138.39 2962.07,138.39 2972,148.31 2972,202.21 2922.45,251.76 2922.45,270.09 U12.B15@2934.84,282.48
  Bottom Layer w4: v1(2840,140) R145.2@2926.38,140
NetR146_2: R146.2 U12.A15 U28.6 | length 377.4
  Top Layer w4: v1(2840,115) 2842.2,112.8 U28.6@2887.8,112.8 2947.8,112.8 2980,145 2980,211.73 U12.A15@2934.84,256.89
  Bottom Layer w4: v1(2840,115) 2865,115 2880,100 R146.2@2926.38,100
NetR151_2: R151.2 U12.D4 | length 169.5
  Top Layer w6: U12.D4@3216.34,333.66 3217.83,335.15 3226.9,335.15 3231.75,340 v1(3235,340)
  Layer 2 w6: v1(3235,340) 3235.3,340.3 3274.7,340.3 3315,300 v1(3340,300)
  Bottom Layer w6: v1(3340,300) R151.2@3366.38,300
NetR152_2: R152.2 U12.C5 | length 270.9
  Top Layer w6: v1(3173.25,300.1) 3175.54,302.4 3182.97,302.4 3188.64,308.07 U12.C5@3190.75,308.07 ; v1(3335,210) v1@3337.3,207.7
  Layer 2 w6: v1(3173.25,300.1) 3221.46,300.1 3278.28,243.29 3278.28,235.85 3304.13,210 v1(3335,210)
  Bottom Layer w6: v1(3335,210) 3335,200 3340,195 R152.2@3366.38,195
NetR153_2: R153.2 U12.E5 | length 223.4
  Top Layer w6: U12.E5@3190.75,359.25 3191.62,358.38 3191.62,343.53 v1(3192.5,342.65)
  Layer 2 w6: v1(3192.5,342.65) 3207.35,342.65 3285,265 v1(3340,265)
  Bottom Layer w6: v1(3340,265) R153.2@3366.38,265
NetR154_2: R154.2 U12.D6 | length 241.2
  Top Layer w6: U12.D6@3165.16,333.66 3167.26,333.66 v1@3173.63,327.3
  Layer 2 w5: 3287.78,240 3287.78,239.79 3297.56,230 v1(3345,230)
  Layer 2 w6: v1(3180,325) 3210,325 3287.78,247.22 3287.78,240
  Bottom Layer w5: v1(3345,230) R154.2@3366.38,230
NetR163.1_2: R163.1.2 U19.1.10 | length 72.2
  Top Layer w6: R163.1.2@1100,1863.62 v1(1100,1905)
  Bottom Layer w4: v1(1100,1905) 1100.39,1904.61 1100.39,1874.88 U19.1.10@1100.79,1874.49
NetR163.2_2: R163.2.2 U19.2.10 | length 64.4
  Top Layer w10: R163.2.2@1100,682.52 v1(1100,720)
  Bottom Layer w10: v1(1100,720) 1100.71,719.29 1100.71,693.46 U19.2.10@1100.79,693.39
NetR164.1_1: R164.1.1 U19.1.32 U26.1.4 | length 229.9
  Top Layer w4: R164.1.1@1076.38,1510 1080.32,1510 1095.44,1525.13 v1(1095.44,1525.62)
  Bottom Layer w4: U19.1.32@1081.1,1685.51 1081.1,1539.96 v1(1095.44,1525.62) 1095.44,1526.58 1116.26,1547.4 U26.1.4@1124.13,1547.4
NetR164.2_1: R164.2.1 U19.2.32 U26.2.4 | length 267.3
  Top Layer w6: R164.2.1@1076.38,328.9 1075,330.28 1075,340.57 1078.51,344.09 v1(1080,344.09)
  Bottom Layer w6: v1(1080,344.09) 1082.3,346.38 1096.34,346.38 U26.2.4@1116.26,366.3 ; U19.2.32@1081.1,504.41 1081.1,497.52 1069.58,486 1063.37,486 1050,472.63 1050,410 1093.7,366.3 U26.2.4@1116.26,366.3 ; U26.2.4@1124.13,366.3 U26.2.4@1116.26,366.3
NetR189.1_1: R189.1.1 U19.1.1 | length 51.2
  Bottom Layer w4: R189.1.1@1013.62,1690 1017.56,1690 1027.37,1699.81 1027.37,1700.77 1037.7,1711.1 U19.1.1@1055.51,1711.1
NetR189.2_1: R189.2.1 U19.2.1 | length 57.3
  Bottom Layer w8: R189.2.1@1013.62,508.9 1013.89,509.16 1044.61,509.16 1053.21,517.76 1053.21,529.08 1054.13,530 U19.2.1@1055.51,530
NetR190.1_1: R190.1.1 U19.1.21 | length 68
  Top Layer w4: R190.1.1@1233.62,1750 1255,1750 v1@1270,1765
  Bottom Layer w4: U19.1.21@1244.49,1770.16 1246.45,1768.19 1261.42,1768.19 1264.14,1765.47 v1(1267.93,1765.47)
NetR190.2_1: R190.2.1 U19.2.21 | length 142.5
  Top Layer w4: R190.2.1@1233.62,568.9 1268.9,568.9 1285,585 1305.71,585 v1(1306.02,584.68)
  Bottom Layer w4: U19.2.21@1244.49,589.06 1297.87,589.06 1302.24,584.68 v1(1306.02,584.68)
NetR203_2: R203.2 U30.35 | length 189.7
  Top Layer w6: R203.2@1650,1463.62 1650,1565 1660,1575 v1(1660,1600)
  Bottom Layer w6: U30.35@1611.85,1602.4 1612.21,1602.04 1657.96,1602.04 v1(1660,1600)
NetR204_2: R204.2 U30.36 | length 227.9
  Top Layer w6: v1(1685,1615) 1685,1585 1690,1580 R204.2@1690,1463.62
  Bottom Layer w6: U30.36@1611.85,1618.15 1678.6,1618.15 1681.75,1615 v1(1685,1615)
NetR205_2: R205.2 U30.37 | length 269.5
  Top Layer w6: v1(1660,1635) 1661,1634 1696,1634 1710,1620 1710,1515 1730,1495 R205.2@1730,1463.62
  Bottom Layer w6: U30.37@1611.85,1633.9 1612.21,1634.26 1659.26,1634.26 v1(1660,1635)
NetR208_2: R208.2 R209.1 U30.70 | length 121.7
  Bottom Layer w6: U30.70@1749.65,2118.15 1749.65,2182.09 1760,2192.44 R208.2@1760,2195 ; R208.2@1760,2196.38 1761.38,2195 R209.1@1800,2195
NetR210_2: R210.2 U30.59 | length 197.1
  Top Layer w6: v1(1690,1875) R210.2@1721.38,1875
  Bottom Layer w6: U30.59@1611.85,1980.35 1612.21,1980 1645,1980 1650,1975 1650,1900 1675,1875 v1(1690,1875)
NetR212_2: R212.2 U30.38 | length 307.4
  Top Layer w6: v1(1685,1650) 1705,1650 1720,1635 1720,1545 1770,1495 R212.2@1770,1463.62
  Bottom Layer w6: U30.38@1611.85,1649.65 1650.81,1649.65 1652.16,1651 1684,1651 v1(1685,1650)
NetS1_1: S1.1 S1.3 U12.U2 | length 749.1
  Top Layer w4: U12.U2@3267.52,666.34 3279.91,678.73 3279.91,696.25 3288.79,705.13 3331.16,705.13 3345.25,719.23 3364.23,719.23 3380,735 v1(3415,735)
  Top Layer w10: S1.1@3684.06,848.54 3741.38,848.54 3747.84,855 v1(3750,855) 3752.16,855 3758.62,848.54 S1.3@3815.94,848.54
  Bottom Layer w4: v1(3415,735) 3700,735 3750,785 v1(3750,855)
NetTP6_1: TP6.1 U12.V1 | length 104.4
  Top Layer w6.45: U12.V1@3293.11,691.93 3331,691.93 3349.07,710 TP6.1@3390,710
NetTP7_1: TP7.1 U12.W1 | length 118.6
  Top Layer w6.45: U12.W1@3293.11,717.52 3310,717.52 3327.52,717.52 3348.77,738.77 3358.77,738.77 TP7.1@3390,770
NetTP8_1: TP8.1 U12.E20 | length 130.1
  Top Layer w4: v1(2680,367) 2762.1,367 2769.84,359.25 U12.E20@2806.89,359.25
NetTP10_1: TP10.1 U12.C18 | length 149.4
  Top Layer w4: TP10.1@2730,270 2811.93,270 2819.64,277.71 2819.64,287.16 2827.35,294.87 2836.8,294.87 2848.13,306.2 2856.2,306.2 U12.C18@2858.07,308.07
NetTP11_1: TP11.1 U12.A19 | length 138.6
  Top Layer w4: TP11.1@2770,150 2787.01,167.01 2797.01,167.01 2810,180 2810,231.16 2818.84,240 2826.78,247.94 2826.78,249.66 2832.48,255.36 U12.A19@2832.48,256.89
NetU3_9: U3.9 U6.14 | length 331.8
  Top Layer w4: U3.9@6059.06,1106.1 6098.9,1106.1 6110.8,1094.2 6202.98,1094.2 6212.18,1085 v1(6215,1085) ; v1(6220,1205) 6220.24,1204.76 6258.82,1204.76 U6.14@6259.06,1204.53
  Bottom Layer w4: v1(6215,1085) 6215,1087.34 6208,1094.34 6208,1193 v1(6220,1205)
NetU4_9: U4.9 U8.14 | length 2361.5
  Top Layer w4: U8.14@5659.06,1204.53 5659.29,1204.76 5684.76,1204.76 v1(5685,1205) ; v1(5685,900) 5700,885 5931.31,885 6066.31,1020 6275.15,1020 6305.15,1050 6364.85,1050 6414.85,1000 6685,1000 6770,915 7143.79,915 7153.79,925 v1(7155,925) ; v1(7165,1230) 7167.5,1232.5 7212.5,1232.5 v1(7215,1235)
  Bottom Layer w4: v1(5685,900) 5670,915 5670,1190 v1(5685,1205) ; v1(7155,925) 7171.29,941.29 7171.29,1006.03 7192,1026.75 7192,1201.69 7165,1228.69 v1(7165,1230) ; v1(7215,1235) 7227.2,1235 7231.1,1231.09 U4.9@7231.1,1219.06
NetU4_14: U4.14 U6.9 | length 1582.8
  Top Layer w4: U6.9@6259.06,1106.1 6259.23,1106.28 6283.38,1106.28 6302.1,1125 6416.21,1125 6421.21,1130 v1(6425,1130) ; v1(6430,985) 6432.34,985 6439.34,992 6681.69,992 6766.69,907 7105.66,907 7112.66,900 v1(7115,900) ; v1(7145,1180) 7196.73,1180 7203.95,1187.21 7251.89,1187.21 7269.11,1170 7325,1170 v1(7330,1175)
  Bottom Layer w4: v1(6425,1130) 6425,990 v1(6430,985) ; v1(7115,900) 7130,915 7130,1078.84 7145,1093.84 v1(7145,1180) ; U4.14@7329.53,1219.06 7329.76,1218.82 7329.76,1175.24 v1(7330,1175)
NetU5_1: U5.1 U7.4 | length 182.3
  Top Layer w4: U5.1@5740.94,1243.9 5711.1,1243.9 5705,1250 5705,1320 5715.71,1330.71 U7.4@5774.41,1330.71
NetU8_9: U8.9 U9.14 | length 2054.8
  Top Layer w4: U9.14@4270.47,1249.06 4270.47,1263.82 4283.65,1277 4430.69,1277 4498,1344.31 4498,1393.96 4538.04,1434 4712.06,1434 4747.06,1399 5087.06,1399 5242.06,1244 5379.15,1244 5600.15,1465 v1(5650,1465) ; v1(5635,1105) 5657.95,1105 U8.9@5659.06,1106.1
  Bottom Layer w4: v1(5635,1105) 5650,1120 v1(5650,1465)
NetU15_1: U15.1 U15.4 U15.10 U15.13 U16.4 | length 540.8
  Top Layer w6: v1(2110,275) 2145,240 ; v1(2145,150) 2145,240 ; v1(2200,150) 2200,185 2145,240
  Bottom Layer w6: U16.4@2074.29,275.59 2074.59,275.3 2109.7,275.3 v1(2110,275) ; U15.1@2140.94,209.06 2140.94,157.3 2145,153.25 v1(2145,150) 2160.63,134.37 U15.13@2160.63,90.94 ; U15.4@2200,209.06 v1(2200,150) 2219.68,130.32 U15.10@2219.68,90.94
NetU20_2: U20.2 U21.4 | length 1965.7
  Top Layer w8: v1(3300,885) U20.2@3300,914.13
  Bottom Layer w8: U21.4@1774.41,174.29 1774.41,199.41 1780,205 2005,205 2045,245 2135,245 2178,288 2373,288 2643.99,558.99 2688.99,558.99 2720,590 2720,730 2877,887 3158,887 3182,863 3278,863 v1(3300,885)
NetU31.1_4: U31.1.4 U31.1.5 U31.1.6 U32.1.4 U32.1.5 U32.1.6 U33.1.3 U34.1.3
  other v1: 7045,685 7045,710 7045,735
NetU31.2_4: U31.2.4 U31.2.5 U31.2.6 U32.2.4 U32.2.5 U32.2.6 U33.2.3 U34.2.3
  other v1: 7521.93,1627.2 7521.93,1652.2 7521.93,1677.2
NetU31.3_4: U31.3.4 U31.3.5 U31.3.6 U32.3.4 U32.3.5 U32.3.6 U33.3.3 U34.3.3
  other v1: 6060.75,685 6060.75,710 6060.75,735
NetU31.4_4: U31.4.4 U31.4.5 U31.4.6 U32.4.4 U32.4.5 U32.4.6 U33.4.3 U34.4.3
  other v1: 6537.68,1627.2 6537.68,1652.2 6537.68,1677.2
NetU31.5_4: U31.5.4 U31.5.5 U31.5.6 U32.5.4 U32.5.5 U32.5.6 U33.5.3 U34.5.3
  other v1: 5553.43,1627.2 5553.43,1652.2 5553.43,1677.2
NetU31.6_4: U31.6.4 U31.6.5 U31.6.6 U32.6.4 U32.6.5 U32.6.6 U33.6.3 U34.6.3
  other v1: 5076.5,685 5076.5,710 5076.5,735
NetU31.7_4: U31.7.4 U31.7.5 U31.7.6 U32.7.4 U32.7.5 U32.7.6 U33.7.3 U34.7.3
  other v1: 4569.17,1627.2 4569.17,1652.2 4569.17,1677.2
NetU31.8_4: U31.8.4 U31.8.5 U31.8.6 U32.8.4 U32.8.5 U32.8.6 U33.8.3 U34.8.3
  other v1: 4092.24,685 4092.24,710 4092.24,735
OSPI0_C\S\: R43.1 U12.L2 U13.C2 | length 498.8
  Top Layer w4: U12.L2@3267.52,512.8 3280.72,526 3315.51,526 3324.5,534.99 3324.5,540.5 3329,545 3475.61,545 3480.61,540 v1(3500,540) ; v1(3710,575) 3710.31,574.68 3710.31,560.31 U13.C2@3710.63,560
  Bottom Layer w4: v1(3500,540) 3515,555 3595,555 3600,550 R43.1@3625,550 ; R43.1@3630,549.5 3634.5,545 3688.3,545 3707.32,564.02 3707.32,572.32 v1(3710,575)
OSPI0_CLK: R62.2 R85.1 U13.B2 | length 269.6
  Top Layer w5: R85.1@3582.72,570 v1(3605,570) ; v1@3699.22,596.44 3700.69,597.9 3707.41,597.9 U13.B2@3708.44,596.87
  Bottom Layer w5: R62.2@3585,570 v1(3605,570) ; v1@3688.84,596.44 v1(3695,596.44)
  Bottom Layer w6: v1(3605,570) 3647,570 3649.12,572.12 ccw(c3643.46,577.78) 3649.12,583.44 3614.53,618.03 cw(c3620.18,623.69) 3614.53,629.34 cw(c3620.18,623.69) 3625.84,629.34 3660.43,594.75 ccw(c3666.09,600.41) 3671.75,594.75 3673.43,596.44 3688.56,596.44 v1@3688.84,596.44
OSPI0_D0: R44.1 R53.1 U12.M3 | length 411.3
  Top Layer w5: 3489.75,485.25 v1(3505,470) R53.1@3553.98,470
  Top Layer w6: v1(3236.13,524.71) 3238.43,527 3238.43,532.78 3241.93,536.28 U12.M3@3241.93,538.39 ; v1(3385,510) 3388.25,510 3394.25,516 3451.75,516 3482.75,485 3489.5,485
  Bottom Layer w5: v1(3236.13,524.71) 3250.84,510 v1(3385,510) ; v1(3505,470) 3507.18,467.82 R44.1@3553.98,467.82
OSPI0_D1: R45.1 R54.1 U12.M2 | length 328.2
  Top Layer w4: U12.M2@3267.52,538.39 3280.72,551.59 3298.24,551.59 3302.63,555.98 3517.13,555.98 3530,543.11 v1(3530,540) 3533.79,540 3538.79,545 R54.1@3553.98,545
  Bottom Layer w4: v1(3530,540) R45.1@3553.98,540
OSPI0_D2: R46.1 R55.1 U12.P1 | length 311.9
  Top Layer w5: v1@3530.93,635 3542.13,623.8 3550.18,623.8 R55.1@3553.98,620
  Top Layer w6: U12.P1@3293.11,589.57 3419.57,589.57 3465,635 v1(3530,635) v1@3530.93,635
  Bottom Layer w5: v1(3530,635) 3533.52,635 3538.52,640 R46.1@3553.98,640
OSPI0_D3: R47.1 R56.1 U12.L1 | length 305.2
  Top Layer w4: 3540.89,495 R56.1@3553.98,495
  Top Layer w6: U12.L1@3293.11,512.8 3357.8,512.8 3371,526 3460.56,526 3491.56,495 v1(3530,495) 3540.89,495
  Bottom Layer w6: v1(3530,495) 3533.25,495 3538.25,490 R47.1@3553.98,490
OSPI0_D4: R48.1 R57.1 U12.R4 | length 395.4
  Top Layer w5: v1(3530,685) 3532.49,682.51 3540.68,682.51 3553.19,670 R57.1@3553.98,670
  Top Layer w6: U12.R4@3216.34,615.16 3216.42,615.08 3239.92,615.08 v1(3240,615)
  Bottom Layer w5: v1@3533.52,685 3538.52,690 R48.1@3553.98,690
  Bottom Layer w6: v1(3240,615) 3254.3,615 3324.3,685 v1(3530,685)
